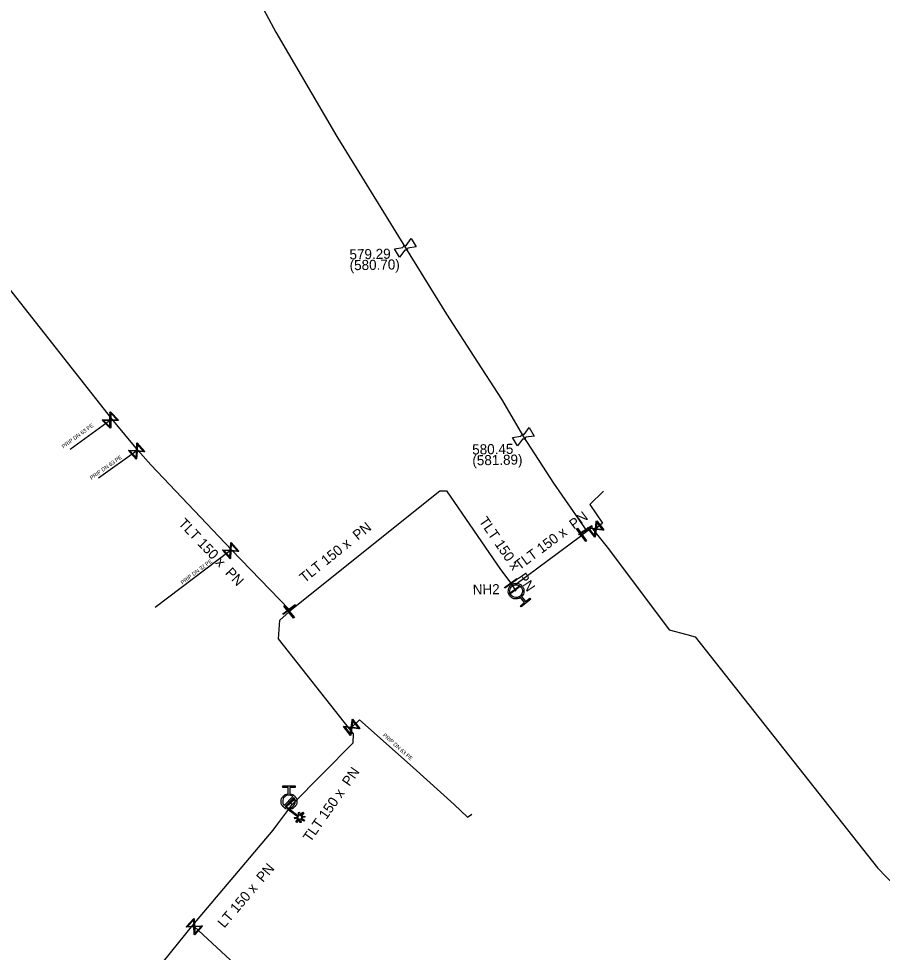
# Model space of a CAD drawing. Extents: x -643842 to -636370, y -1119190 to -1110210.
# Drawn here: x -641769.3 to -641657.8, y -1114879.5 to -1114758.9 of the extents above; entities that cross this region are included whole.
import ezdxf

# ---------------------------------------------------------------- set-up
doc = ezdxf.new("R2010")
doc.units = 0
for name, color, linetype in [('2', 7, 'Continuous'), ('22', 7, 'Continuous'), ('Default', 7, 'Continuous'), ('Level 16', 7, 'Continuous'), ('Level 20', 7, 'Continuous'), ('Level 21', 7, 'Continuous'), ('Level 23', 7, 'Continuous'), ('Level 27', 7, 'Continuous'), ('Level 28', 7, 'Continuous'), ('Level 32', 7, 'Continuous'), ('Level 33', 7, 'Continuous')]:
    doc.layers.add(name, color=color, linetype=linetype)

msp = doc.modelspace()

# ---------------------------------------------------------------- linework, layer by layer
at = {"layer": '2'}
msp.add_lwpolyline([(-641732.82, -1114862.11), (-641732.38, -1114862.43), (-641732.48, -1114862.56), (-641732.91, -1114862.24), (-641732.84, -1114862.71), (-641732.99, -1114862.73), (-641733.06, -1114862.27), (-641733.4, -1114862.73), (-641733.53, -1114862.64), (-641733.18, -1114862.17), (-641733.65, -1114862.24), (-641733.67, -1114862.09), (-641733.21, -1114862.02), (-641734.49, -1114861.07), (-641734.4, -1114860.95), (-641733.12, -1114861.89), (-641733.19, -1114861.43), (-641733.03, -1114861.4), (-641732.96, -1114861.87), (-641732.62, -1114861.4), (-641732.49, -1114861.49), (-641732.83, -1114861.96), (-641732.37, -1114861.89), (-641732.35, -1114862.04), (-641732.82, -1114862.11)], dxfattribs=at)
at = {"layer": 'Default'}
for points in [[(-641719.68, -1114788.47), (-641719.67, -1114788.42), (-641719.64, -1114788.37), (-641719.6, -1114788.3), (-641719.53, -1114788.25), (-641719.46, -1114788.21), (-641719.38, -1114788.21), (-641719.32, -1114788.21), (-641719.27, -1114788.22)], [(-641719.06, -1114788.57), (-641719.07, -1114788.62), (-641719.09, -1114788.67), (-641719.14, -1114788.74), (-641719.21, -1114788.79), (-641719.28, -1114788.83), (-641719.36, -1114788.83), (-641719.41, -1114788.83), (-641719.46, -1114788.82)], [(-641704.44, -1114812.85), (-641704.43, -1114812.8), (-641704.4, -1114812.75), (-641704.36, -1114812.68), (-641704.29, -1114812.64), (-641704.22, -1114812.6), (-641704.13, -1114812.6), (-641704.08, -1114812.6), (-641704.03, -1114812.61)], [(-641703.82, -1114812.97), (-641703.83, -1114813.02), (-641703.86, -1114813.06), (-641703.9, -1114813.14), (-641703.97, -1114813.18), (-641704.04, -1114813.22), (-641704.13, -1114813.22), (-641704.18, -1114813.22), (-641704.23, -1114813.21)], [(-641704.51, -1114833.68), (-641704.8, -1114833.88), (-641705.17, -1114833.85), (-641705.58, -1114833.81), (-641705.84, -1114833.49), (-641706.11, -1114833.17), (-641706.07, -1114832.75), (-641706.03, -1114832.34), (-641705.71, -1114832.08), (-641705.39, -1114831.82), (-641704.98, -1114831.85), (-641704.56, -1114831.89), (-641704.3, -1114832.21), (-641704.04, -1114832.53), (-641704.07, -1114832.94), (-641704.11, -1114833.31), (-641704.36, -1114833.56)], [(-641704.55, -1114833.48), (-641704.29, -1114833.26), (-641704.26, -1114832.93), (-641704.23, -1114832.59), (-641704.44, -1114832.33), (-641704.66, -1114832.07), (-641704.99, -1114832.04), (-641705.32, -1114832.01), (-641705.58, -1114832.22), (-641705.84, -1114832.44), (-641705.88, -1114832.77), (-641705.91, -1114833.11), (-641705.69, -1114833.37), (-641705.48, -1114833.63), (-641705.14, -1114833.66), (-641704.81, -1114833.69), (-641704.55, -1114833.48)], [(-641734.31, -1114859.01), (-641733.95, -1114859.04), (-641733.69, -1114859.3), (-641733.4, -1114859.6), (-641733.4, -1114860.01), (-641733.4, -1114860.43), (-641733.69, -1114860.72), (-641733.99, -1114861.01), (-641734.4, -1114861.01), (-641734.81, -1114861.01), (-641735.11, -1114860.72), (-641735.4, -1114860.43), (-641735.4, -1114860.01), (-641735.4, -1114859.6), (-641735.11, -1114859.3), (-641734.85, -1114859.04), (-641734.49, -1114859.01)], [(-641733.89, -1114859.37), (-641734.11, -1114859.2), (-641734.4, -1114859.2), (-641734.74, -1114859.2), (-641734.98, -1114859.43), (-641735.21, -1114859.67), (-641735.21, -1114860.01), (-641735.21, -1114860.3), (-641735.04, -1114860.52)], [(-641734.91, -1114860.65), (-641734.69, -1114860.82), (-641734.4, -1114860.82), (-641734.07, -1114860.82), (-641733.83, -1114860.58), (-641733.59, -1114860.35), (-641733.59, -1114860.01), (-641733.59, -1114859.72), (-641733.76, -1114859.5)]]:
    msp.add_open_spline(points, degree=3, dxfattribs=at)
at = {"layer": 'Level 16'}
for points in [[(-641757.47, -1114809.7), (-641756.41, -1114810.76), (-641756.46, -1114810.81), (-641756.59, -1114810.81), (-641757.43, -1114810.8), (-641757.43, -1114811.77), (-641757.48, -1114811.82), (-641758.53, -1114810.76), (-641758.49, -1114810.71), (-641757.52, -1114810.72), (-641757.51, -1114809.88), (-641757.52, -1114809.75), (-641757.47, -1114809.7)], [(-641757.43, -1114809.88), (-641757.43, -1114810.72), (-641756.59, -1114810.72), (-641757.43, -1114809.88)], [(-641757.52, -1114811.65), (-641757.52, -1114810.8), (-641758.36, -1114810.8), (-641757.52, -1114811.65)], [(-641753.99, -1114813.69), (-641753, -1114814.82), (-641753.05, -1114814.86), (-641753.18, -1114814.85), (-641754.02, -1114814.8), (-641754.08, -1114815.76), (-641754.13, -1114815.81), (-641755.12, -1114814.68), (-641755.07, -1114814.64), (-641754.1, -1114814.7), (-641754.05, -1114813.86), (-641754.04, -1114813.74), (-641753.99, -1114813.69)], [(-641753.96, -1114813.87), (-641754.01, -1114814.71), (-641753.18, -1114814.76), (-641753.96, -1114813.87)], [(-641754.16, -1114815.63), (-641754.11, -1114814.79), (-641754.94, -1114814.74), (-641754.16, -1114815.63)], [(-641694.66, -1114823.77), (-641693.74, -1114824.95), (-641693.79, -1114824.99), (-641693.92, -1114824.97), (-641694.75, -1114824.87), (-641694.87, -1114825.83), (-641694.92, -1114825.87), (-641695.84, -1114824.69), (-641695.79, -1114824.65), (-641694.83, -1114824.77), (-641694.73, -1114823.94), (-641694.71, -1114823.81), (-641694.66, -1114823.77)], [(-641697.15, -1114824.74), (-641695.97, -1114826.35), (-641696.07, -1114826.42), (-641697.25, -1114824.81), (-641697.15, -1114824.74)], [(-641696.97, -1114825.47), (-641695.3, -1114824.36), (-641695.23, -1114824.47), (-641696.9, -1114825.58), (-641696.97, -1114825.47)], [(-641694.94, -1114825.7), (-641694.84, -1114824.86), (-641695.67, -1114824.76), (-641694.94, -1114825.7)], [(-641694.64, -1114823.95), (-641694.74, -1114824.78), (-641693.91, -1114824.88), (-641694.64, -1114823.95)], [(-641741.88, -1114826.56), (-641740.89, -1114827.69), (-641740.94, -1114827.73), (-641741.06, -1114827.72), (-641741.9, -1114827.67), (-641741.96, -1114828.64), (-641742.01, -1114828.68), (-641743, -1114827.56), (-641742.95, -1114827.51), (-641741.98, -1114827.57), (-641741.93, -1114826.74), (-641741.93, -1114826.61), (-641741.88, -1114826.56)], [(-641741.85, -1114826.74), (-641741.9, -1114827.58), (-641741.06, -1114827.63), (-641741.85, -1114826.74)], [(-641742.04, -1114828.5), (-641741.99, -1114827.66), (-641742.83, -1114827.61), (-641742.04, -1114828.5)], [(-641704.9, -1114831.3), (-641706.51, -1114832.48), (-641706.58, -1114832.38), (-641704.97, -1114831.2), (-641704.9, -1114831.3)], [(-641704.56, -1114832.23), (-641705.76, -1114833.14), (-641705.82, -1114833.07), (-641704.62, -1114832.16), (-641704.56, -1114832.23)], [(-641733.55, -1114834.66), (-641735.14, -1114835.88), (-641735.21, -1114835.78), (-641733.62, -1114834.56), (-641733.55, -1114834.66)], [(-641733.8, -1114836.32), (-641735.07, -1114834.78), (-641734.98, -1114834.7), (-641733.71, -1114836.24), (-641733.8, -1114836.32)], [(-641726.18, -1114849.4), (-641725.27, -1114850.59), (-641725.32, -1114850.63), (-641725.45, -1114850.61), (-641726.28, -1114850.5), (-641726.41, -1114851.46), (-641726.46, -1114851.5), (-641727.37, -1114850.31), (-641727.32, -1114850.27), (-641726.36, -1114850.4), (-641726.24, -1114849.57), (-641726.23, -1114849.44), (-641726.18, -1114849.4)], [(-641726.48, -1114851.32), (-641726.37, -1114850.49), (-641727.2, -1114850.37), (-641726.48, -1114851.32)], [(-641726.16, -1114849.58), (-641726.27, -1114850.41), (-641725.44, -1114850.52), (-641726.16, -1114849.58)], [(-641733.64, -1114859.7), (-641734.74, -1114860.72), (-641734.8, -1114860.66), (-641733.7, -1114859.64), (-641733.64, -1114859.7)], [(-641745.57, -1114876.11), (-641746.58, -1114877.22), (-641746.63, -1114877.18), (-641746.63, -1114877.05), (-641746.67, -1114876.21), (-641747.64, -1114876.25), (-641747.69, -1114876.21), (-641746.68, -1114875.1), (-641746.63, -1114875.15), (-641746.59, -1114876.12), (-641745.75, -1114876.08), (-641745.62, -1114876.07), (-641745.57, -1114876.11)], [(-641747.52, -1114876.16), (-641746.68, -1114876.12), (-641746.71, -1114875.28), (-641747.52, -1114876.16)], [(-641745.75, -1114876.17), (-641746.58, -1114876.21), (-641746.55, -1114877.04), (-641745.75, -1114876.17)]]:
    msp.add_lwpolyline(points, dxfattribs=at)
at = {"layer": 'Level 21'}
for points in [[(-641773.45, -1114677.98), (-641767.95, -1114693.02), (-641761.02, -1114710.08), (-641756.03, -1114721.53), (-641749.76, -1114734.57), (-641746, -1114742.1), (-641743.7, -1114746.39), (-641740.74, -1114752), (-641736.11, -1114760.67), (-641728.22, -1114774.15), (-641719.37, -1114788.52), (-641714.07, -1114797.07), (-641710.52, -1114802.56), (-641706.97, -1114808.06), (-641704.13, -1114812.91), (-641700.26, -1114818.89), (-641695.95, -1114825.11), (-641695.69, -1114824.95), (-641695.55, -1114824.83)], [(-641734.25, -1114835.36), (-641734.38, -1114835.22), (-641741.81, -1114827.52), (-641752.25, -1114816.52), (-641753.94, -1114814.65), (-641757.27, -1114810.61), (-641771.12, -1114793.05), (-641785.71, -1114777.32), (-641790.3, -1114772.73)], [(-641734.25, -1114835.36), (-641714.9, -1114819.88), (-641714.06, -1114819.91), (-641707.08, -1114830.07), (-641705.74, -1114831.84), (-641705.5, -1114832.17)], [(-641695.55, -1114824.83), (-641695.3, -1114824.64), (-641695.02, -1114825), (-641693.14, -1114827.38), (-641685.31, -1114837.85), (-641683.04, -1114838.45)], [(-641705.5, -1114832.17), (-641705.12, -1114831.94), (-641696.76, -1114825.75), (-641696.61, -1114825.58), (-641696.26, -1114825.35), (-641695.95, -1114825.11)], [(-641734.44, -1114861.01), (-641734, -1114860.38), (-641726.12, -1114852.42), (-641726.07, -1114851.29), (-641726.57, -1114850.65), (-641735.75, -1114839.02), (-641735.57, -1114836.61), (-641734.39, -1114835.51), (-641734.25, -1114835.36)], [(-641683.04, -1114838.45), (-641681.96, -1114838.73), (-641658.38, -1114868.59), (-641649.21, -1114878.11), (-641635.01, -1114896.04), (-641630.23, -1114904.09), (-641629.62, -1114904.74), (-641627.03, -1114907.5), (-641606.99, -1114928.85), (-641592.39, -1114941.41), (-641591.23, -1114942.12), (-641579.65, -1114941.79), (-641560, -1114940.9)], [(-641817.48, -1114967.4), (-641816.61, -1114965.45), (-641811.33, -1114957.65), (-641801.44, -1114943.64), (-641796.45, -1114936.03), (-641790.5, -1114927.86), (-641782.43, -1114916.53), (-641775.83, -1114909.48), (-641773.76, -1114908.01), (-641772.55, -1114907.69), (-641766.29, -1114900.06), (-641765.21, -1114898.73), (-641746.84, -1114875.96), (-641736.43, -1114863.71), (-641735.84, -1114862.9), (-641734.44, -1114861.01)]]:
    msp.add_lwpolyline(points, dxfattribs=at)
at = {"layer": 'Level 23'}
for points in [[(-641757.27, -1114810.61), (-641757.47, -1114810.76), (-641762.65, -1114814.56)], [(-641753.94, -1114814.65), (-641754.06, -1114814.75), (-641759.02, -1114818.27)], [(-641693.79, -1114819.95), (-641695.54, -1114821.68), (-641693.91, -1114824.09), (-641695.02, -1114825)], [(-641741.81, -1114827.52), (-641741.95, -1114827.62), (-641751.68, -1114834.95)], [(-641705.07, -1114832.85), (-641705.19, -1114832.65), (-641705.5, -1114832.17)], [(-641726.57, -1114850.65), (-641726.32, -1114850.45), (-641725.29, -1114849.48), (-641718.36, -1114855.64), (-641713.07, -1114860.42), (-641711.34, -1114862.04), (-641710.78, -1114861.63)], [(-641734, -1114860.38), (-641734.22, -1114860.18), (-641734.4, -1114860.01)], [(-641746.84, -1114875.96), (-641746.63, -1114876.16), (-641732.68, -1114889.06)]]:
    msp.add_lwpolyline(points, dxfattribs=at)
at = {"layer": 'Level 28'}
for points in [[(-641719.27, -1114788.22), (-641718.63, -1114787.33)], [(-641718.63, -1114787.33), (-641717.98, -1114788.4), (-641719.06, -1114788.57)], [(-641719.46, -1114788.82), (-641720.11, -1114789.71), (-641720.76, -1114788.64), (-641719.68, -1114788.47)], [(-641704.03, -1114812.61), (-641703.37, -1114811.74)], [(-641703.37, -1114811.74), (-641702.74, -1114812.82), (-641703.82, -1114812.97)], [(-641704.23, -1114813.21), (-641704.89, -1114814.08), (-641705.52, -1114813), (-641704.44, -1114812.85)]]:
    msp.add_lwpolyline(points, dxfattribs=at)
at = {"layer": 'Level 33'}
for points in [[(-641704.36, -1114833.56), (-641703.84, -1114834.19), (-641703.31, -1114833.75), (-641703.19, -1114833.89), (-641704.4, -1114834.89), (-641704.52, -1114834.75), (-641703.98, -1114834.31), (-641704.51, -1114833.68)], [(-641734.49, -1114859.01), (-641734.49, -1114858.19), (-641735.18, -1114858.19), (-641735.18, -1114858.01), (-641733.62, -1114858.01), (-641733.62, -1114858.19), (-641734.31, -1114858.19), (-641734.31, -1114859.01)], [(-641735.04, -1114860.52), (-641733.89, -1114859.37)], [(-641733.76, -1114859.5), (-641734.91, -1114860.65)]]:
    msp.add_lwpolyline(points, dxfattribs=at)

# ---------------------------------------------------------------- texts
at = {"layer": '22'}
for s, rotation, p in [('PRIP DN 63 PE', 36.2641, (-641763.52, -1114814.44)), ('PRIP DN 63 PE', 35.3625, (-641759.9, -1114818.5)), ('PRIP DN 32 PE', 36.9716, (-641748.16, -1114832.01)), ('PRIP DN 63 PE', 318.4142, (-641722.34, -1114851.51))]:
    msp.add_text(s, height=0.5, rotation=rotation, dxfattribs=at).set_placement(p)
at = {"layer": 'Level 20'}
for s, rotation, p in [('TLT 150 x  PN ', 36.7509, (-641704.65, -1114830.19)), ('TLT 150 x  PN ', 313.5038, (-641748.77, -1114824.18)), ('TLT 150 x  PN ', 304.4894, (-641709.93, -1114823.81)), ('TLT 150 x  PN ', 38.6598, (-641732.39, -1114831.83)), ('TLT 150 x  PN ', 55.0691, (-641731.63, -1114865.35)), ('LT 150 x  PN ', 49.6454, (-641742.76, -1114876.43))]:
    msp.add_text(s, height=1.3, rotation=rotation, dxfattribs=at).set_placement(p)
at = {"layer": 'Level 27'}
for s, p in [('579.29', (-641726.58, -1114790.02)), ('(580.70)', (-641726.56, -1114791.42)), ('580.45', (-641710.73, -1114815.21)), ('(581.89)', (-641710.71, -1114816.61))]:
    msp.add_text(s, height=1.3, rotation=1, dxfattribs=at).set_placement(p)
at = {"layer": 'Level 32'}
msp.add_text('NH2', height=1.3, rotation=1, dxfattribs=at).set_placement((-641710.66, -1114833.3))

doc.saveas('drawing.dxf')
